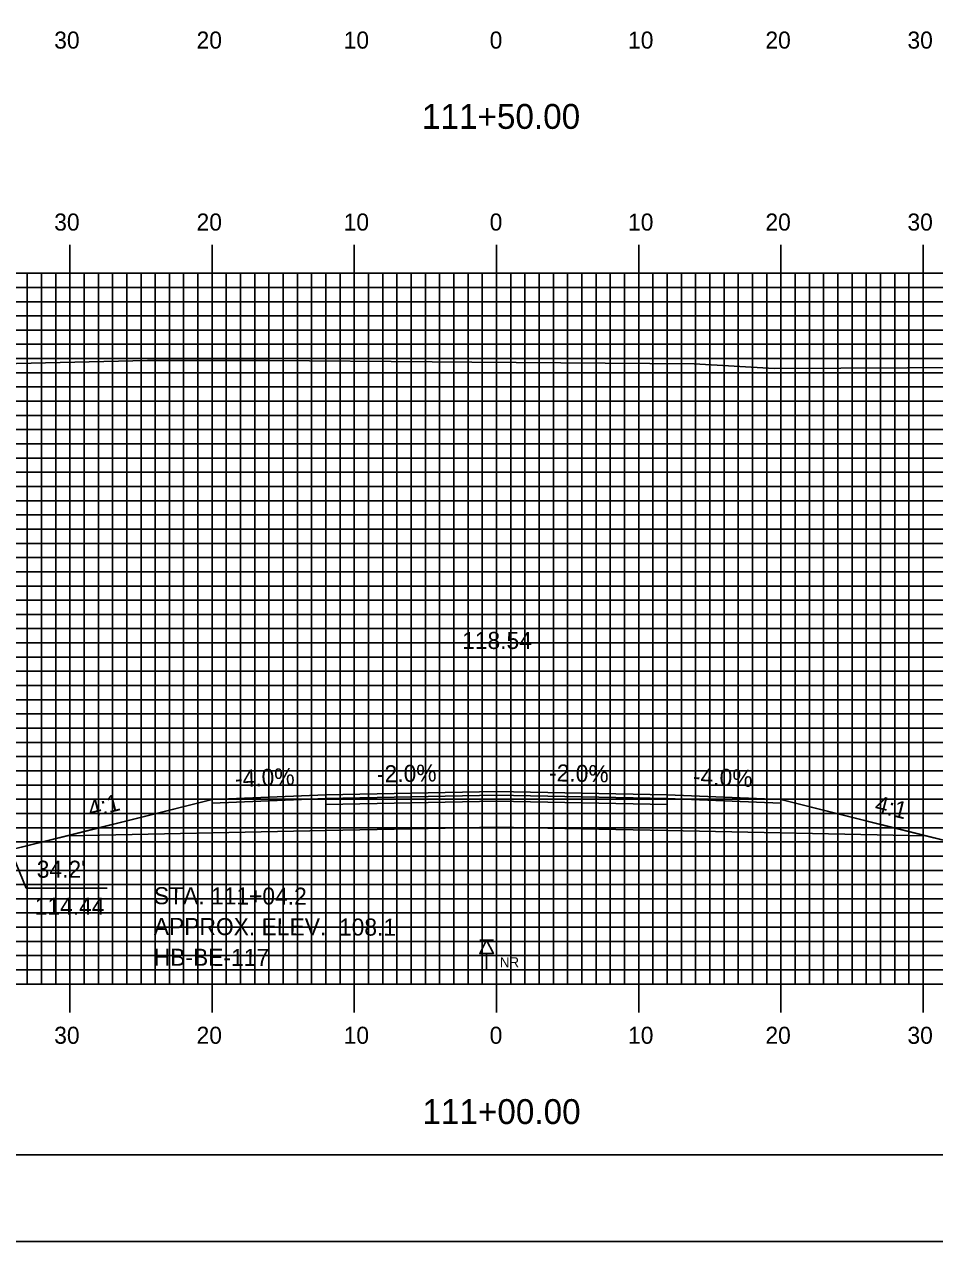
# Model space of a CAD drawing. Extents: x 1769661 to 1770005, y 442591 to 442811.
# Drawn here: x 1769793.8 to 1769857.8, y 442590.5 to 442676.2 of the extents above; entities that cross this region are included whole.
import ezdxf

# ---------------------------------------------------------------- set-up
doc = ezdxf.new("R2010")
doc.units = 0
for name, color, linetype in [('ANNOTATION', 7, 'Continuous'), ('BORDER', 7, 'Continuous'), ('BORING - NO REFUSAL', 7, 'Continuous'), ('D_Roadway_Centerline', 7, 'Continuous'), ('D_Roadway_Centerline_Text', 7, 'Continuous'), ('D_Roadway_Edge_Shoulder', 7, 'Continuous'), ('D_Roadway_Edge_TW', 7, 'Continuous'), ('D_Roadway_Pavement', 7, 'Continuous'), ('D_Roadway_SlopeLines', 7, 'Continuous'), ('D_Roadway_SubGrade', 7, 'Continuous'), ('H_V ANNOTATION', 7, 'Continuous'), ('MAJOR', 7, 'Continuous'), ('MINOR', 7, 'Continuous'), ('PLOT BOUNDARY', 7, 'Continuous'), ('S_Roadway_Centerline', 7, 'Continuous')]:
    doc.layers.add(name, color=color, linetype=linetype)

msp = doc.modelspace()

# ---------------------------------------------------------------- linework, layer by layer
at = {"layer": 'ANNOTATION'}
msp.add_lwpolyline([(1769799.64, 442615.417), (1769793.948, 442615.417), (1769792.841, 442618.102)], dxfattribs=at)
at = {"layer": 'BORDER'}
msp.add_lwpolyline([(1769677.415, 442596.665), (1769997.415, 442596.665), (1769997.415, 442806.665), (1769677.415, 442806.665)], close=True, dxfattribs=at)
at = {"layer": 'BORING - NO REFUSAL'}
for p, q in [((1769826.795, 442611.765), (1769825.835, 442611.765)), ((1769826.315, 442610.806), (1769826.315, 442609.747))]:
    msp.add_line(p, q, dxfattribs=at)
msp.add_lwpolyline([(1769826.315, 442611.765), (1769826.795, 442610.806), (1769825.835, 442610.806)], close=True, dxfattribs=at)
at = {"layer": 'D_Roadway_Centerline'}
msp.add_lwpolyline([(1769732.367, 442651.098), (1769733.617, 442651.066), (1769734.046, 442650.989), (1769734.867, 442650.84), (1769736.117, 442650.418), (1769737.367, 442649.801), (1769737.37, 442649.8), (1769756.633, 442638.792), (1769792.841, 442618.102), (1769796.841, 442619.102), (1769807.015, 442621.646), (1769815.015, 442621.966), (1769827.015, 442622.206), (1769839.015, 442621.966), (1769847.015, 442621.646), (1769854.846, 442619.688), (1769857.189, 442619.102), (1769861.189, 442618.102), (1769916.315, 442649.603), (1769917.565, 442650.224), (1769918.815, 442650.66), (1769919.51, 442650.799), (1769920.064, 442650.91), (1769921.314, 442650.974)], dxfattribs=at)
at = {"layer": 'D_Roadway_Edge_Shoulder'}
for points in [[(1769815.015, 442621.966), (1769807.015, 442621.646), (1769807.015, 442621.396), (1769815.015, 442621.716)], [(1769839.015, 442621.966), (1769847.015, 442621.646), (1769847.015, 442621.396), (1769839.015, 442621.716)]]:
    msp.add_lwpolyline(points, close=True, dxfattribs=at)
at = {"layer": 'D_Roadway_Edge_TW'}
msp.add_lwpolyline([(1769815.015, 442621.716), (1769815.015, 442621.966), (1769827.015, 442622.206), (1769839.015, 442621.966), (1769839.015, 442621.716), (1769827.015, 442621.956)], close=True, dxfattribs=at)
at = {"layer": 'D_Roadway_Pavement'}
msp.add_lwpolyline([(1769815.015, 442621.299), (1769815.015, 442621.716), (1769827.015, 442621.956), (1769839.015, 442621.716), (1769839.015, 442621.299), (1769827.015, 442621.539)], close=True, dxfattribs=at)
at = {"layer": 'D_Roadway_SlopeLines'}
for points in [[(1769807.015, 442621.646), (1769792.841, 442618.102)], [(1769847.015, 442621.646), (1769861.189, 442618.102)]]:
    msp.add_lwpolyline(points, dxfattribs=at)
at = {"layer": 'D_Roadway_SubGrade'}
msp.add_lwpolyline([(1769815.015, 442619.466), (1769796.841, 442619.102), (1769807.015, 442621.646), (1769807.015, 442621.396), (1769815.015, 442621.716), (1769827.015, 442621.956), (1769839.015, 442621.716), (1769847.015, 442621.396), (1769847.015, 442621.646), (1769857.189, 442619.102), (1769839.015, 442619.466), (1769827.015, 442619.706)], close=True, dxfattribs=at)
at = {"layer": 'MAJOR'}
for p, q in [((1769797.015, 442660.669), (1769797.015, 442658.665)), ((1769807.015, 442660.669), (1769807.015, 442658.665)), ((1769817.015, 442660.669), (1769817.015, 442658.665)), ((1769827.015, 442660.669), (1769827.015, 442658.665)), ((1769837.015, 442660.669), (1769837.015, 442658.665)), ((1769847.015, 442660.669), (1769847.015, 442658.665)), ((1769857.015, 442660.669), (1769857.015, 442658.665)), ((1769687.015, 442658.665), (1769967.015, 442658.665)), ((1769687.015, 442658.665), (1769967.015, 442658.665)), ((1769797.015, 442608.665), (1769797.015, 442658.665)), ((1769807.015, 442608.665), (1769807.015, 442658.665)), ((1769817.015, 442608.665), (1769817.015, 442658.665)), ((1769827.015, 442608.665), (1769827.015, 442658.665)), ((1769837.015, 442608.665), (1769837.015, 442658.665)), ((1769847.015, 442608.665), (1769847.015, 442658.665)), ((1769857.015, 442608.665), (1769857.015, 442658.665)), ((1769687.015, 442653.665), (1769967.015, 442653.665)), ((1769687.015, 442648.665), (1769967.015, 442648.665)), ((1769687.015, 442643.665), (1769967.015, 442643.665)), ((1769687.015, 442638.665), (1769967.015, 442638.665)), ((1769687.015, 442633.665), (1769967.015, 442633.665)), ((1769687.015, 442628.665), (1769967.015, 442628.665)), ((1769687.015, 442623.665), (1769967.015, 442623.665)), ((1769687.015, 442618.665), (1769967.015, 442618.665)), ((1769687.015, 442613.665), (1769967.015, 442613.665)), ((1769687.015, 442608.665), (1769967.015, 442608.665)), ((1769687.015, 442608.665), (1769967.015, 442608.665)), ((1769797.015, 442606.661), (1769797.015, 442608.665)), ((1769807.015, 442606.661), (1769807.015, 442608.665)), ((1769817.015, 442606.661), (1769817.015, 442608.665)), ((1769827.015, 442606.661), (1769827.015, 442608.665)), ((1769837.015, 442606.661), (1769837.015, 442608.665)), ((1769847.015, 442606.661), (1769847.015, 442608.665)), ((1769857.015, 442606.661), (1769857.015, 442608.665))]:
    msp.add_line(p, q, dxfattribs=at)
at = {"layer": 'MINOR'}
for p, q in [((1769794.015, 442608.665), (1769794.015, 442658.665)), ((1769795.015, 442608.665), (1769795.015, 442658.665)), ((1769796.015, 442608.665), (1769796.015, 442658.665)), ((1769798.015, 442608.665), (1769798.015, 442658.665)), ((1769799.015, 442608.665), (1769799.015, 442658.665)), ((1769800.015, 442608.665), (1769800.015, 442658.665)), ((1769801.015, 442608.665), (1769801.015, 442658.665)), ((1769802.015, 442608.665), (1769802.015, 442658.665)), ((1769803.015, 442608.665), (1769803.015, 442658.665)), ((1769804.015, 442608.665), (1769804.015, 442658.665)), ((1769805.015, 442608.665), (1769805.015, 442658.665)), ((1769806.015, 442608.665), (1769806.015, 442658.665)), ((1769808.015, 442608.665), (1769808.015, 442658.665)), ((1769809.015, 442608.665), (1769809.015, 442658.665)), ((1769810.015, 442608.665), (1769810.015, 442658.665)), ((1769811.015, 442608.665), (1769811.015, 442658.665)), ((1769812.015, 442608.665), (1769812.015, 442658.665)), ((1769813.015, 442608.665), (1769813.015, 442658.665)), ((1769814.015, 442608.665), (1769814.015, 442658.665)), ((1769815.015, 442608.665), (1769815.015, 442658.665)), ((1769816.015, 442608.665), (1769816.015, 442658.665)), ((1769818.015, 442608.665), (1769818.015, 442658.665)), ((1769819.015, 442608.665), (1769819.015, 442658.665)), ((1769820.015, 442608.665), (1769820.015, 442658.665)), ((1769821.015, 442608.665), (1769821.015, 442658.665)), ((1769822.015, 442608.665), (1769822.015, 442658.665)), ((1769823.015, 442608.665), (1769823.015, 442658.665)), ((1769824.015, 442608.665), (1769824.015, 442658.665)), ((1769825.015, 442608.665), (1769825.015, 442658.665)), ((1769826.015, 442608.665), (1769826.015, 442658.665)), ((1769828.015, 442608.665), (1769828.015, 442658.665)), ((1769829.015, 442608.665), (1769829.015, 442658.665)), ((1769830.015, 442608.665), (1769830.015, 442658.665)), ((1769831.015, 442608.665), (1769831.015, 442658.665)), ((1769832.015, 442608.665), (1769832.015, 442658.665)), ((1769833.015, 442608.665), (1769833.015, 442658.665)), ((1769834.015, 442608.665), (1769834.015, 442658.665)), ((1769835.015, 442608.665), (1769835.015, 442658.665)), ((1769836.015, 442608.665), (1769836.015, 442658.665)), ((1769838.015, 442608.665), (1769838.015, 442658.665)), ((1769839.015, 442608.665), (1769839.015, 442658.665)), ((1769840.015, 442608.665), (1769840.015, 442658.665)), ((1769841.015, 442608.665), (1769841.015, 442658.665)), ((1769842.015, 442608.665), (1769842.015, 442658.665)), ((1769843.015, 442608.665), (1769843.015, 442658.665)), ((1769844.015, 442608.665), (1769844.015, 442658.665)), ((1769845.015, 442608.665), (1769845.015, 442658.665)), ((1769846.015, 442608.665), (1769846.015, 442658.665)), ((1769848.015, 442608.665), (1769848.015, 442658.665)), ((1769849.015, 442608.665), (1769849.015, 442658.665)), ((1769850.015, 442608.665), (1769850.015, 442658.665)), ((1769851.015, 442608.665), (1769851.015, 442658.665)), ((1769852.015, 442608.665), (1769852.015, 442658.665)), ((1769853.015, 442608.665), (1769853.015, 442658.665)), ((1769854.015, 442608.665), (1769854.015, 442658.665)), ((1769855.015, 442608.665), (1769855.015, 442658.665)), ((1769856.015, 442608.665), (1769856.015, 442658.665)), ((1769687.015, 442657.665), (1769967.015, 442657.665)), ((1769687.015, 442656.665), (1769967.015, 442656.665)), ((1769687.015, 442655.665), (1769967.015, 442655.665)), ((1769687.015, 442654.665), (1769967.015, 442654.665)), ((1769687.015, 442652.665), (1769967.015, 442652.665)), ((1769687.015, 442651.665), (1769967.015, 442651.665)), ((1769687.015, 442650.665), (1769967.015, 442650.665)), ((1769687.015, 442649.665), (1769967.015, 442649.665)), ((1769687.015, 442647.665), (1769967.015, 442647.665)), ((1769687.015, 442646.665), (1769967.015, 442646.665)), ((1769687.015, 442645.665), (1769967.015, 442645.665)), ((1769687.015, 442644.665), (1769967.015, 442644.665)), ((1769687.015, 442642.665), (1769967.015, 442642.665)), ((1769687.015, 442641.665), (1769967.015, 442641.665)), ((1769687.015, 442640.665), (1769967.015, 442640.665)), ((1769687.015, 442639.665), (1769967.015, 442639.665)), ((1769687.015, 442637.665), (1769967.015, 442637.665)), ((1769687.015, 442636.665), (1769967.015, 442636.665)), ((1769687.015, 442635.665), (1769967.015, 442635.665)), ((1769687.015, 442634.665), (1769967.015, 442634.665)), ((1769687.015, 442632.665), (1769967.015, 442632.665)), ((1769687.015, 442631.665), (1769967.015, 442631.665)), ((1769687.015, 442630.665), (1769967.015, 442630.665)), ((1769687.015, 442629.665), (1769967.015, 442629.665)), ((1769687.015, 442627.665), (1769967.015, 442627.665)), ((1769687.015, 442626.665), (1769967.015, 442626.665)), ((1769687.015, 442625.665), (1769967.015, 442625.665)), ((1769687.015, 442624.665), (1769967.015, 442624.665)), ((1769687.015, 442622.665), (1769967.015, 442622.665)), ((1769687.015, 442621.665), (1769967.015, 442621.665)), ((1769687.015, 442620.665), (1769967.015, 442620.665)), ((1769687.015, 442619.665), (1769967.015, 442619.665)), ((1769687.015, 442617.665), (1769967.015, 442617.665)), ((1769687.015, 442616.665), (1769967.015, 442616.665)), ((1769687.015, 442615.665), (1769967.015, 442615.665)), ((1769687.015, 442614.665), (1769967.015, 442614.665)), ((1769687.015, 442612.665), (1769967.015, 442612.665)), ((1769687.015, 442611.665), (1769967.015, 442611.665)), ((1769687.015, 442610.665), (1769967.015, 442610.665)), ((1769687.015, 442609.665), (1769967.015, 442609.665))]:
    msp.add_line(p, q, dxfattribs=at)
at = {"layer": 'PLOT BOUNDARY'}
msp.add_lwpolyline([(1769661.228, 442590.547), (1770001.228, 442590.547), (1770001.228, 442810.547), (1769661.228, 442810.547)], close=True, dxfattribs=at)
at = {"layer": 'S_Roadway_Centerline'}
msp.add_lwpolyline([(1769687.015, 442649.293), (1769687.167, 442649.298), (1769704.645, 442650.096), (1769707.209, 442650.162), (1769716.906, 442650.478), (1769725.648, 442650.726), (1769731.355, 442651.044), (1769744.901, 442651.762), (1769762.614, 442651.923), (1769763.542, 442651.932), (1769764.174, 442651.952), (1769766.643, 442651.943), (1769783.404, 442652.101), (1769793.271, 442652.323), (1769802.466, 442652.537), (1769810.991, 442652.523), (1769822.479, 442652.429), (1769825.284, 442652.418), (1769840.906, 442652.283), (1769846.533, 442651.967), (1769855.905, 442652.007), (1769858.8, 442652.029)], dxfattribs=at)

# ---------------------------------------------------------------- texts
at = {"layer": 'ANNOTATION'}
for s, rotation, p in [('-4.0%', 2.29062, (1769808.647, 442622.513)), ('-2.0%', 1.14577, (1769818.621, 442622.839)), ('-2.0%', 358.85423, (1769830.701, 442622.933)), ('-4.0%', 357.70938, (1769840.807, 442622.696)), ('4:1', 14.03781, (1769798.464, 442620.37)), ('4:1', 345.96291, (1769853.542, 442620.792))]:
    msp.add_text(s, height=1.2, rotation=rotation, dxfattribs=at).set_placement(p)
for s, p in [("34.2'", (1769794.683, 442616.143)), ('114.44', (1769794.539, 442613.543))]:
    msp.add_text(s, height=1.2, dxfattribs=at).set_placement(p)
at = {"layer": 'BORING - NO REFUSAL'}
for s, p in [('STA. 111+04.2', (1769802.921, 442614.282)), ('APPROX. ELEV.  108.1', (1769802.914, 442612.122)), ('HB-BE-117', (1769802.907, 442609.962))]:
    msp.add_text(s, height=1.2, rotation=359.81416, dxfattribs=at).set_placement(p)
msp.add_text('NR', height=0.6998, dxfattribs=at).set_placement((1769827.248, 442609.85))
at = {"layer": 'D_Roadway_Centerline'}
for s, p in [('C', (1769827.01, 442622.206)), ('L', (1769827.015, 442622.199))]:
    msp.add_text(s, height=0.0146, dxfattribs=at).set_placement(p)
at = {"layer": 'D_Roadway_Centerline_Text'}
msp.add_text('118.54', height=1.2, dxfattribs=at).set_placement((1769824.596, 442632.236))
at = {"layer": 'H_V ANNOTATION'}
for s, height, p in [('30', 1.2, (1769795.912, 442674.465)), ('20', 1.2, (1769805.923, 442674.465)), ('10', 1.2, (1769816.266, 442674.465)), ('0', 1.2, (1769826.533, 442674.465)), ('10', 1.2, (1769836.266, 442674.465)), ('20', 1.2, (1769845.923, 442674.465)), ('30', 1.2, (1769855.912, 442674.465)), ('111+50.00', 1.75, (1769821.772, 442668.821)), ('30', 1.2, (1769795.912, 442661.665)), ('20', 1.2, (1769805.923, 442661.665)), ('10', 1.2, (1769816.266, 442661.665)), ('0', 1.2, (1769826.533, 442661.665)), ('10', 1.2, (1769836.266, 442661.665)), ('20', 1.2, (1769845.923, 442661.665)), ('30', 1.2, (1769855.912, 442661.665)), ('30', 1.2, (1769795.912, 442604.465)), ('20', 1.2, (1769805.923, 442604.465)), ('10', 1.2, (1769816.266, 442604.465)), ('0', 1.2, (1769826.533, 442604.465)), ('10', 1.2, (1769836.266, 442604.465)), ('20', 1.2, (1769845.923, 442604.465)), ('30', 1.2, (1769855.912, 442604.465)), ('111+00.00', 1.75, (1769821.803, 442598.821))]:
    msp.add_text(s, height=height, dxfattribs=at).set_placement(p)

doc.saveas('drawing.dxf')
